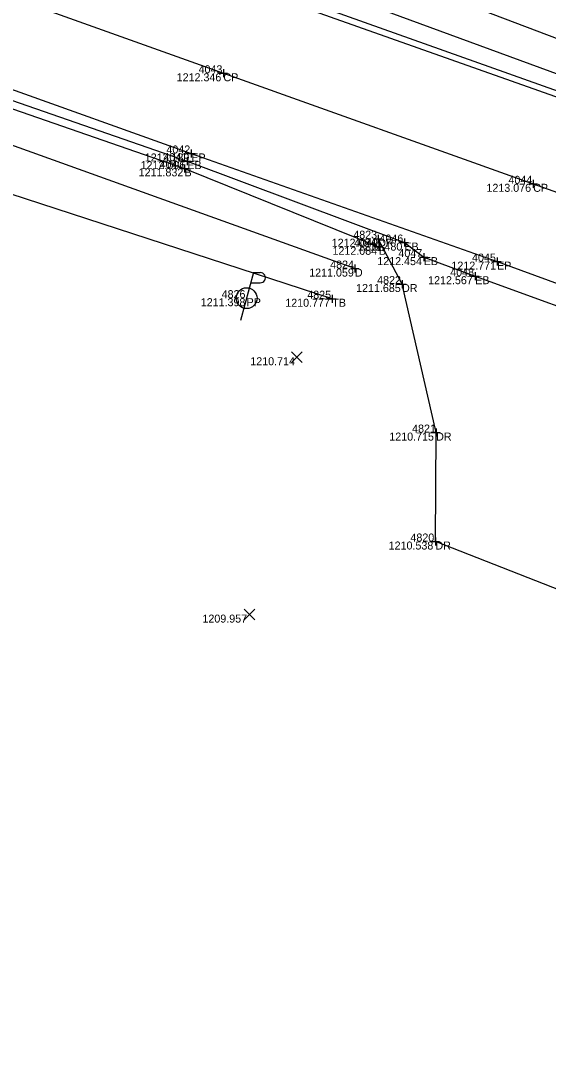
# Model space of a CAD drawing. Extents: x 2044996 to 2050343, y 455232 to 458054.
# Drawn here: x 2047903.2 to 2047969.1, y 456761.8 to 456892.7 of the extents above; entities that cross this region are included whole.
import ezdxf

# ---------------------------------------------------------------- set-up
doc = ezdxf.new("R2010")
doc.units = 0
for name, color, linetype in [('DR_X_Ditch', 7, 'Continuous'), ('DT_X_Contour_Minor', 7, 'Continuous'), ('DT_X_Contour_Text', 7, 'Continuous'), ('DT_X_Spot_Elev', 7, 'Continuous'), ('DT_X_Triangles', 7, 'Continuous'), ('DT_X_Void', 7, 'Continuous'), ('PV_X_COP', 7, 'Continuous'), ('PV_X_Driveway', 7, 'Continuous'), ('PV_X_EOP', 7, 'Continuous'), ('PV_X_Shoulder_Aggregate', 7, 'Continuous'), ('SV_X_Break_Lines', 7, 'Continuous'), ('SV_X_Top_of_Bank', 7, 'Continuous'), ('UT_X_Electric_Cells', 7, 'Continuous')]:
    doc.layers.add(name, color=color, linetype=linetype)

msp = doc.modelspace()

# ---------------------------------------------------------------- linework, layer by layer
at = {"layer": 'DR_X_Ditch'}
for points in [[(2047780.51, 456960.13), (2047826.93, 456942.06), (2047870.38, 456926.94), (2047917.77, 456909.91), (2047942.94, 456900.89), (2047986.92, 456884.17), (2048032.77, 456867.49), (2048075.71, 456852.37), (2048118.48, 456836.63), (2048162.27, 456821), (2048204.38, 456806.34), (2048252.02, 456790.17), (2048298.22, 456772.41), (2048313.77, 456769.57), (2048332, 456765.35)], [(2047944.96, 456861.76), (2047899.25, 456878.16), (2047861.64, 456891.96), (2047815.35, 456909.09), (2047774.86, 456921.86), (2047729.93, 456938.25), (2047691.42, 456950.76), (2047669.22, 456956.37), (2047658.75, 456950.98), (2047651.4, 456909.49), (2047651.98, 456861.4), (2047653.43, 456816.89), (2047656.94, 456761.43), (2047657.83, 456718.94), (2047659.36, 456677.43), (2047660.77, 456628.12), (2047661.37, 456577.1), (2047662.68, 456519.59), (2047665.25, 456466.46), (2047666.16, 456418.54), (2047665.56, 456406.95)]]:
    msp.add_lwpolyline(points, dxfattribs=at)
at = {"layer": 'DT_X_Spot_Elev'}
for p, q in [((2047937.03, 456850.02), (2047938.36, 456851.35)), ((2047937.03, 456851.35), (2047938.36, 456850.02)), ((2047931.12, 456817.86), (2047932.46, 456819.19)), ((2047931.12, 456819.19), (2047932.46, 456817.86))]:
    msp.add_line(p, q, dxfattribs=at)
at = {"layer": 'DT_X_Void'}
for p, q in [((2047928.03, 456886.16), (2047929.03, 456886.16)), ((2047928.53, 456886.66), (2047928.53, 456885.66)), ((2047928.53, 456886.16), (2047928.53, 456886.16)), ((2047924.52, 456876.64), (2047924.52, 456875.64)), ((2047923.52, 456875.18), (2047924.52, 456875.18)), ((2047924.02, 456876.14), (2047925.02, 456876.14)), ((2047924.02, 456875.68), (2047924.02, 456874.68)), ((2047924.02, 456875.18), (2047924.02, 456875.18)), ((2047924.52, 456876.14), (2047924.52, 456876.14)), ((2047923.17, 456874.28), (2047924.17, 456874.28)), ((2047923.67, 456874.78), (2047923.67, 456873.78)), ((2047923.67, 456874.28), (2047923.67, 456874.28)), ((2047967.24, 456872.85), (2047967.24, 456871.85)), ((2047966.74, 456872.35), (2047967.74, 456872.35)), ((2047967.24, 456872.35), (2047967.24, 456872.35)), ((2047947.87, 456865.99), (2047947.87, 456864.99)), ((2047947.37, 456865.49), (2047948.37, 456865.49)), ((2047947.87, 456865.49), (2047947.87, 456865.49)), ((2047947.96, 456864.98), (2047947.96, 456863.98)), ((2047950.65, 456865.01), (2047951.65, 456865.01)), ((2047951.15, 456865.51), (2047951.15, 456864.51)), ((2047951.15, 456865.01), (2047951.15, 456865.01)), ((2047947.46, 456864.48), (2047948.46, 456864.48)), ((2047947.96, 456864.48), (2047947.96, 456864.48)), ((2047953.56, 456863.69), (2047953.56, 456862.69)), ((2047944.96, 456862.26), (2047944.96, 456861.26)), ((2047953.06, 456863.19), (2047954.06, 456863.19)), ((2047953.56, 456863.19), (2047953.56, 456863.19)), ((2047962.23, 456862.63), (2047963.23, 456862.63)), ((2047962.73, 456863.13), (2047962.73, 456862.13)), ((2047962.73, 456862.63), (2047962.73, 456862.63)), ((2047944.46, 456861.76), (2047945.46, 456861.76)), ((2047944.96, 456861.76), (2047944.96, 456861.76)), ((2047959.49, 456860.81), (2047960.49, 456860.81)), ((2047959.99, 456861.31), (2047959.99, 456860.31)), ((2047959.99, 456860.81), (2047959.99, 456860.81)), ((2047950.35, 456859.83), (2047951.35, 456859.83)), ((2047950.85, 456860.33), (2047950.85, 456859.33)), ((2047950.85, 456859.83), (2047950.85, 456859.83)), ((2047942.14, 456858.49), (2047942.14, 456857.49)), ((2047941.64, 456857.99), (2047942.64, 456857.99)), ((2047942.14, 456857.99), (2047942.14, 456857.99)), ((2047954.61, 456841.27), (2047955.61, 456841.27)), ((2047955.11, 456841.77), (2047955.11, 456840.77)), ((2047955.11, 456841.27), (2047955.11, 456841.27)), ((2047955.02, 456828.16), (2047955.02, 456827.16)), ((2047954.52, 456827.66), (2047955.52, 456827.66)), ((2047955.02, 456827.66), (2047955.02, 456827.66))]:
    msp.add_line(p, q, dxfattribs=at)
at = {"layer": 'PV_X_COP'}
msp.add_lwpolyline([(2047721.58, 456961.45), (2047764.11, 456945.53), (2047805.42, 456930.56), (2047848.07, 456915.19), (2047886.38, 456901.23), (2047928.53, 456886.16), (2047967.24, 456872.35), (2048004.2, 456859.18), (2048043.3, 456845.25), (2048086.02, 456829.64), (2048125.99, 456815.39), (2048168.62, 456799.78), (2048207.67, 456785.38), (2048251.12, 456769.74), (2048292.61, 456754.36), (2048333.81, 456739.22), (2048373.81, 456724.48), (2048417.09, 456709.08), (2048458.61, 456693.82), (2048498.86, 456678.79), (2048537.43, 456664.8), (2048579.13, 456649.5), (2048615.78, 456636.27)], dxfattribs=at)
at = {"layer": 'PV_X_Driveway'}
msp.add_lwpolyline([(2047981.91, 456852.94), (2047977.75, 456849.13), (2047974.9, 456819.89), (2047955.02, 456827.66), (2047955.11, 456841.27), (2047950.85, 456859.83), (2047947.87, 456865.49)], dxfattribs=at)
at = {"layer": 'PV_X_EOP'}
for p, q in [((2047981.85, 456879.05), (2047937.77, 456894.62)), ((2047883.44, 456890.83), (2047924.52, 456876.14)), ((2047924.52, 456876.14), (2047962.73, 456862.63)), ((2047962.73, 456862.63), (2047999.58, 456849.23))]:
    msp.add_line(p, q, dxfattribs=at)
at = {"layer": 'PV_X_Shoulder_Aggregate'}
for points in [[(2048620.54, 456647.12), (2048583.12, 456660.67), (2048539.73, 456676.45), (2048498.23, 456691.52), (2048454.17, 456707.97), (2048410.24, 456724.1), (2048369.4, 456738.65), (2048329.21, 456753.43), (2048288.45, 456768.21), (2048244.06, 456784.69), (2048200.54, 456800.78), (2048154.81, 456817.47), (2048112.55, 456832.71), (2048067.31, 456849.18), (2048026.51, 456863.76), (2047982.25, 456879.67), (2047938.09, 456895.41), (2047894.6, 456910.89), (2047855.83, 456924.74), (2047813.34, 456939.9), (2047765.41, 456957.6), (2047718.77, 456974.89)], [(2047718.66, 456948.27), (2047759.49, 456933.93), (2047801.19, 456918.92), (2047842.96, 456903.9), (2047883.05, 456889.4), (2047924.02, 456875.18), (2047951.15, 456865.01), (2047953.56, 456863.19), (2047959.99, 456860.81), (2047979.02, 456853.88), (2047983.62, 456853.54), (2047999.27, 456848.34), (2048040.39, 456833.65), (2048080.57, 456819.36)]]:
    msp.add_lwpolyline(points, dxfattribs=at)
at = {"layer": 'SV_X_Break_Lines'}
for points in [[(2048620.73, 456648.35), (2048583.39, 456661.98), (2048539.9, 456677.65), (2048498.37, 456692.73), (2048454.2, 456708.99), (2048410.48, 456724.96), (2048370.07, 456739.9), (2048329.65, 456754.5), (2048288.87, 456769.18), (2048244.36, 456785.65), (2048200.73, 456801.81), (2048154.72, 456818.61), (2048112.67, 456833.97), (2048067.63, 456850.21), (2048026.62, 456865.12), (2047982.64, 456881.49), (2047938.6, 456897.69), (2047895.04, 456913.55), (2047856.96, 456927.13), (2047813.61, 456942.44), (2047766.63, 456959.74), (2047718.99, 456976.33)], [(2047652.8, 456955.87), (2047664.54, 456962.83), (2047671.52, 456961.88), (2047676.87, 456960.65), (2047718.46, 456947.45), (2047759.36, 456932.8), (2047800.99, 456917.68), (2047842.23, 456903.25), (2047882.81, 456888.44), (2047923.67, 456874.28), (2047947.96, 456864.48)]]:
    msp.add_lwpolyline(points, dxfattribs=at)
at = {"layer": 'SV_X_Top_of_Bank'}
msp.add_lwpolyline([(2047942.14, 456857.99), (2047898.01, 456872.36), (2047859.06, 456885.19), (2047815.47, 456901.27), (2047771.85, 456916.42), (2047729.97, 456932.49), (2047688.22, 456947.3), (2047669.99, 456955.17), (2047661.07, 456948.62), (2047656.72, 456911.9), (2047659.76, 456864.17), (2047662.28, 456815.7), (2047662.72, 456763.39), (2047662.48, 456719.38), (2047665.2, 456677.14), (2047665.7, 456629.87), (2047667.28, 456578.15), (2047668.69, 456520.88), (2047669.88, 456466.8), (2047671, 456408.28)], dxfattribs=at)
at = {"layer": 'UT_X_Electric_Cells'}
for p, q in [((2047932.29, 456861.26), (2047930.68, 456855.26)), ((2047932.29, 456861.26), (2047933.14, 456861.26)), ((2047931.95, 456859.99), (2047933.14, 456859.99))]:
    msp.add_line(p, q, dxfattribs=at)
msp.add_circle((2047931.43, 456858.06), 1.3, dxfattribs=at)
msp.add_arc((2047933.15, 456860.62), 0.638, 268.8767, 91.1233, dxfattribs=at)

# ---------------------------------------------------------------- texts
at = {"layer": 'DT_X_Contour_Minor'}
for s, p in [('1212.346', (2047922.69, 456885.16)), ('1212.096', (2047918.18, 456874.18)), ('1212.189', (2047918.7, 456875.14)), ('1211.832', (2047917.94, 456873.28)), ('1213.076', (2047961.4, 456871.35)), ('1212.024', (2047942.06, 456864.49)), ('1212.480', (2047945.31, 456864.01)), ('1212.084', (2047942.16, 456863.48)), ('1212.454', (2047947.76, 456862.19)), ('1212.771', (2047957.02, 456861.63)), ('1211.059', (2047939.25, 456860.76)), ('1212.567', (2047954.11, 456859.81)), ('1211.685', (2047945.11, 456858.83)), ('1211.398', (2047925.7, 456857.06)), ('1210.777', (2047936.26, 456856.99)), ('1210.714', (2047931.89, 456849.68)), ('1210.715', (2047949.26, 456840.27)), ('1210.538', (2047949.18, 456826.66)), ('1209.957', (2047925.91, 456817.53))]:
    msp.add_text(s, height=1, dxfattribs=at).set_placement(p)
at = {"layer": 'DT_X_Contour_Text'}
for s, p in [('CP', (2047928.53, 456885.16)), ('EB', (2047924.02, 456874.18)), ('EP', (2047924.52, 456875.14)), ('B', (2047923.67, 456873.28)), ('CP', (2047967.24, 456871.35)), ('DR', (2047947.87, 456864.49)), ('EB', (2047951.15, 456864.01)), ('B', (2047947.96, 456863.48)), ('EB', (2047953.56, 456862.19)), ('EP', (2047962.73, 456861.63)), ('D', (2047944.96, 456860.76)), ('EB', (2047959.99, 456859.81)), ('DR', (2047950.85, 456858.83)), ('PP', (2047931.43, 456857.06)), ('TB', (2047942.14, 456856.99)), ('DR', (2047955.11, 456840.27)), ('DR', (2047955.02, 456826.66))]:
    msp.add_text(s, height=1, dxfattribs=at).set_placement(p)
at = {"layer": 'DT_X_Triangles'}
for s, p in [('4043', (2047925.43, 456886.16)), ('4042', (2047921.41, 456876.14)), ('4040', (2047920.55, 456874.28)), ('4041', (2047921.03, 456875.18)), ('4044', (2047964.15, 456872.35)), ('4823', (2047944.76, 456865.49)), ('4046', (2047948.03, 456865.01)), ('4049', (2047944.86, 456864.48)), ('4047', (2047950.4, 456863.19)), ('4045', (2047959.6, 456862.63)), ('4824', (2047941.87, 456861.76)), ('4822', (2047947.74, 456859.83)), ('4048', (2047956.87, 456860.81)), ('4826', (2047928.31, 456858.06)), ('4825', (2047939.01, 456857.99)), ('4821', (2047952.11, 456841.27)), ('4820', (2047951.9, 456827.66))]:
    msp.add_text(s, height=1, dxfattribs=at).set_placement(p)

doc.saveas('drawing.dxf')
